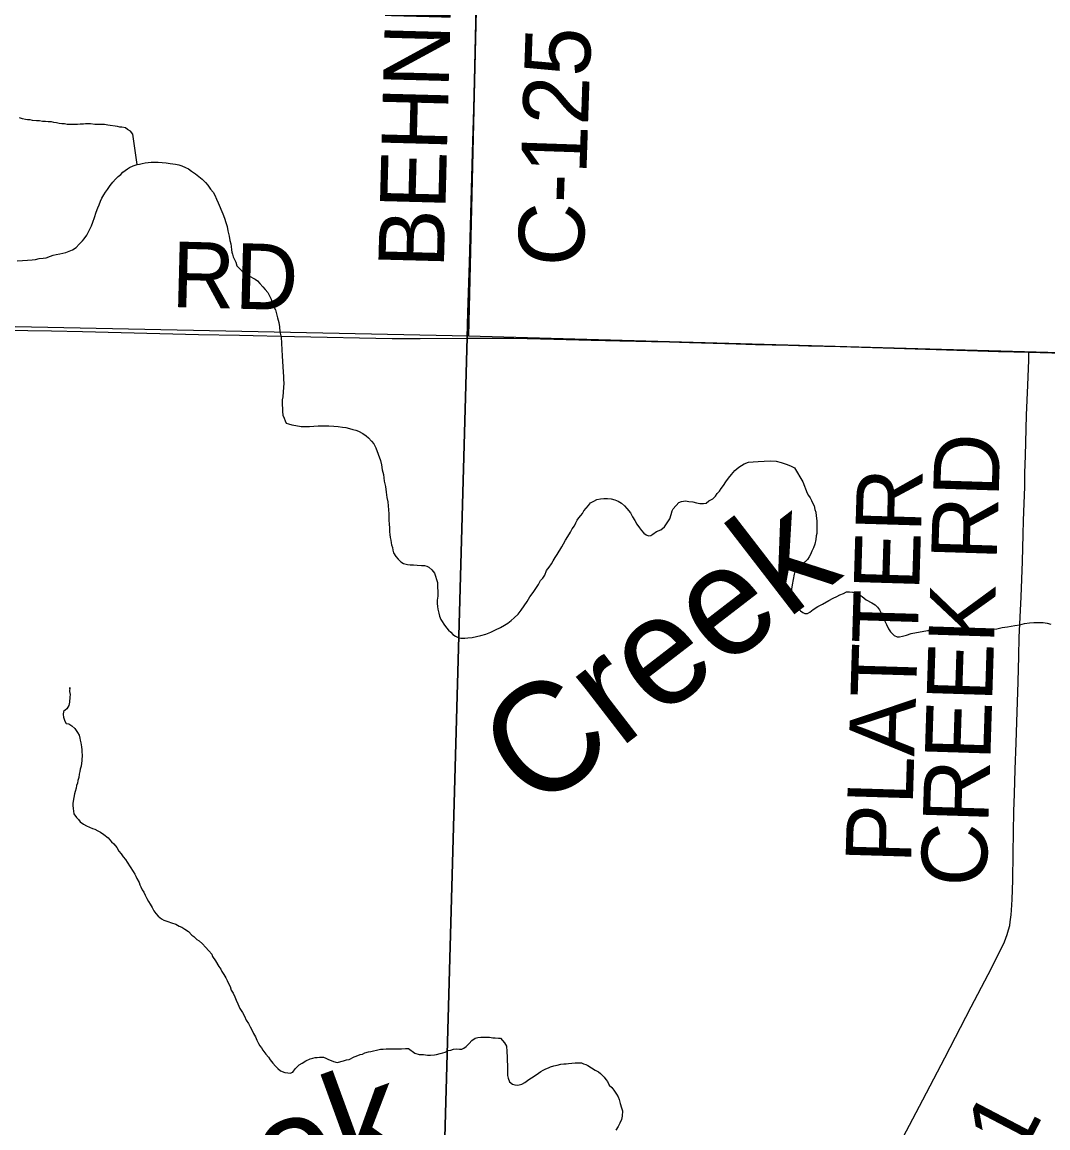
# Model space of a CAD drawing. Extents: x 2.4 to 73.1, y 4.5 to 25.6.
# Drawn here: x 30.3384 to 30.7828, y 21.8149 to 22.2941 of the extents above; entities that cross this region are included whole.
import ezdxf

# ---------------------------------------------------------------- set-up
doc = ezdxf.new("R2010")
doc.units = 0
for name, color, linetype in [('GM_X_County_Road', 7, 'Continuous'), ('GM_X_County_Road_Text', 7, 'Continuous'), ('GM_X_Interchange_Ramps', 7, 'Continuous'), ('GM_X_Minor_River', 7, 'Continuous'), ('GM_X_Minor_River_Text', 7, 'Continuous'), ('GM_X_Section', 7, 'Continuous'), ('GM_X_Township', 7, 'Continuous'), ('GM_X_Township_Road', 7, 'Continuous'), ('GM_X_Township_Road_Text', 7, 'Continuous')]:
    doc.layers.add(name, color=color, linetype=linetype)

msp = doc.modelspace()

# ---------------------------------------------------------------- linework, layer by layer
at = {"layer": 'GM_X_County_Road'}
for points in [[(30.53135, 22.15713), (30.53168, 22.16802), (30.53233, 22.18946), (30.53363, 22.23731), (30.53416, 22.25626), (30.53467, 22.2746), (30.53494, 22.28734), (30.53559, 22.31904), (30.53645, 22.3498), (30.53724, 22.38306), (30.53771, 22.40201), (30.53826, 22.42594), (30.53893, 22.45515), (30.53952, 22.48281), (30.54007, 22.5027), (30.54091, 22.54341), (30.5412, 22.55491), (30.54272, 22.61986), (30.54351, 22.65), (30.54377, 22.65984)], [(30.02726, 22.16709), (30.03446, 22.16694), (30.06678, 22.16622), (30.08667, 22.16574), (30.11464, 22.16515), (30.16499, 22.164), (30.19824, 22.16321), (30.21658, 22.16286), (30.25946, 22.16202), (30.27935, 22.16155), (30.29458, 22.16116), (30.32007, 22.16074), (30.35114, 22.16022), (30.36451, 22.15997), (30.41485, 22.15876), (30.43256, 22.15839), (30.45648, 22.15783), (30.49875, 22.15699), (30.51088, 22.1569), (30.53135, 22.15713)], [(30.53135, 22.15713), (30.54112, 22.15717), (30.55139, 22.15708), (30.56879, 22.15669), (30.58495, 22.15624), (30.59738, 22.15594), (30.61105, 22.15566), (30.61882, 22.15548), (30.62752, 22.15528), (30.63777, 22.15501), (30.64771, 22.15471), (30.6561, 22.15443), (30.67037, 22.15401), (30.67907, 22.15382), (30.69274, 22.15347), (30.7207, 22.15258), (30.73438, 22.15219), (30.7614, 22.15137), (30.77457, 22.15103)], [(30.77457, 22.15103), (30.78937, 22.15064), (30.81392, 22.14998), (30.8307, 22.14948), (30.84965, 22.14881), (30.85741, 22.14855), (30.86829, 22.14817), (30.88785, 22.14753), (30.8981, 22.14719), (30.90928, 22.14687), (30.92668, 22.14638), (30.94345, 22.14576), (30.96501, 22.14514), (30.986, 22.14442), (31.00185, 22.14396), (31.02143, 22.14323), (31.02525, 22.14309)]]:
    msp.add_lwpolyline(points, dxfattribs=at)
at = {"layer": 'GM_X_Interchange_Ramps'}
msp.add_lwpolyline([(30.32928, 21.66006), (30.35104, 21.65971), (30.3697, 21.65926), (30.4615, 21.65688), (30.51723, 21.65555), (30.53123, 22.15741), (30.53156, 22.1683), (30.53221, 22.18973), (30.53352, 22.23759), (30.53404, 22.25654), (30.53455, 22.27487), (30.53482, 22.28762), (30.53547, 22.31932)], dxfattribs=at)
at = {"layer": 'GM_X_Minor_River'}
for points in [[(30.38825, 22.23232), (30.38636, 22.24547), (30.38543, 22.24681), (30.38411, 22.24759), (30.38317, 22.24818), (30.38166, 22.24858), (30.3807, 22.24859), (30.37976, 22.2488), (30.37558, 22.24944), (30.37406, 22.24965), (30.37216, 22.24968), (30.37083, 22.2497), (30.36988, 22.24972), (30.36798, 22.24994), (30.36703, 22.24995), (30.36589, 22.24997), (30.36494, 22.2498), (30.36361, 22.24982), (30.36246, 22.24965), (30.36113, 22.24967), (30.35942, 22.2497), (30.3579, 22.24972), (30.35676, 22.24993), (30.35562, 22.24995), (30.35448, 22.25016), (30.35335, 22.25036), (30.35221, 22.25057), (30.35107, 22.25078), (30.34974, 22.2508), (30.3486, 22.25101), (30.34727, 22.25103), (30.34594, 22.25124), (30.34461, 22.25126), (30.3429, 22.25148), (30.34196, 22.25169), (30.34081, 22.2517), (30.33987, 22.25191), (30.33854, 22.25212), (30.33721, 22.25252)], [(30.33624, 22.1906), (30.33853, 22.19075), (30.34081, 22.1909), (30.34272, 22.19106), (30.34424, 22.19123), (30.34577, 22.19158), (30.34748, 22.19175), (30.34882, 22.19192), (30.35073, 22.19265), (30.35187, 22.19301), (30.35321, 22.19337), (30.35474, 22.19372), (30.35607, 22.19389), (30.35741, 22.19425), (30.35875, 22.1948), (30.36028, 22.19534), (30.36182, 22.19646), (30.36317, 22.19777), (30.36453, 22.19926), (30.3653, 22.2002), (30.36647, 22.2017), (30.36843, 22.20585), (30.36903, 22.20736), (30.36982, 22.20944), (30.37043, 22.21171), (30.37122, 22.2136), (30.37181, 22.21492), (30.3724, 22.21643), (30.37299, 22.21775), (30.37378, 22.21926), (30.37456, 22.22038), (30.37533, 22.22151), (30.3765, 22.2232), (30.37767, 22.2247), (30.37883, 22.22602), (30.37999, 22.22714), (30.38114, 22.22807), (30.38211, 22.229), (30.38403, 22.23049), (30.38499, 22.23105), (30.38653, 22.23178), (30.38825, 22.23232), (30.3892, 22.2325), (30.39035, 22.23286), (30.39168, 22.23303), (30.39301, 22.2332), (30.39435, 22.23337), (30.39587, 22.23334), (30.39739, 22.23332), (30.3991, 22.23329)], [(30.3991, 22.23329), (30.40081, 22.23307), (30.40252, 22.23286), (30.40479, 22.23244), (30.40631, 22.23222), (30.40764, 22.23182), (30.40915, 22.23104), (30.41047, 22.23045), (30.41179, 22.22948), (30.41348, 22.22831), (30.41498, 22.22715), (30.41648, 22.22598), (30.41779, 22.22463), (30.41892, 22.22347), (30.42003, 22.22174), (30.42115, 22.2204), (30.42189, 22.21906), (30.42263, 22.21733), (30.42336, 22.2158), (30.42538, 22.21102), (30.42611, 22.20911), (30.42665, 22.2072), (30.42719, 22.20548), (30.42755, 22.20357), (30.42808, 22.20129), (30.42843, 22.19938), (30.42879, 22.19804), (30.42896, 22.1969), (30.42913, 22.19538), (30.4293, 22.19443), (30.42948, 22.19347), (30.42984, 22.19233), (30.43039, 22.19118), (30.43094, 22.19003), (30.43149, 22.1885), (30.43262, 22.18734), (30.43374, 22.18618), (30.43486, 22.18522), (30.43618, 22.18444), (30.4375, 22.18365), (30.43844, 22.18307), (30.43939, 22.18267), (30.44033, 22.1819), (30.44145, 22.18074), (30.44276, 22.17939), (30.44369, 22.17823), (30.44481, 22.17689), (30.44574, 22.17516), (30.44629, 22.17401), (30.44665, 22.17268), (30.44738, 22.17095), (30.44812, 22.16942), (30.44866, 22.1677), (30.44902, 22.16599), (30.44955, 22.16389), (30.4499, 22.16198), (30.45006, 22.15989), (30.4506, 22.1576), (30.45075, 22.15494), (30.45089, 22.15209), (30.45104, 22.14943), (30.4515, 22.14239), (30.45166, 22.14049), (30.45164, 22.13916), (30.4518, 22.13763), (30.45158, 22.13574), (30.45155, 22.13384), (30.45133, 22.13175), (30.45112, 22.13042), (30.4511, 22.12909), (30.45108, 22.12815), (30.45125, 22.12681), (30.45123, 22.12529), (30.4514, 22.12377), (30.45195, 22.12243), (30.45231, 22.12129), (30.45287, 22.12033), (30.45381, 22.11993), (30.45532, 22.11953), (30.45703, 22.11931), (30.45931, 22.11889), (30.46121, 22.11886), (30.46292, 22.11883), (30.46483, 22.11899), (30.46673, 22.11915), (30.46882, 22.11912), (30.47129, 22.11908), (30.47339, 22.11905), (30.47528, 22.11883), (30.47718, 22.11861), (30.4787, 22.11839), (30.48021, 22.11799), (30.48173, 22.11758), (30.48305, 22.11718), (30.48419, 22.11678), (30.48608, 22.1158), (30.48739, 22.11483), (30.48852, 22.11386), (30.48983, 22.11251), (30.49076, 22.11136), (30.49168, 22.10963)], [(30.49168, 22.10963), (30.49369, 22.10409), (30.49404, 22.10218), (30.49439, 22.10009), (30.49492, 22.09799), (30.49526, 22.09513), (30.4958, 22.09285), (30.49614, 22.09037), (30.49648, 22.08809), (30.49683, 22.08618), (30.497, 22.08447), (30.49716, 22.08275), (30.49732, 22.08104), (30.4973, 22.07971), (30.49728, 22.07819), (30.49744, 22.07648), (30.49761, 22.07496), (30.49758, 22.07325), (30.49775, 22.0721), (30.49792, 22.07077), (30.49809, 22.06963), (30.49827, 22.06849), (30.49844, 22.06753), (30.4988, 22.06639), (30.49898, 22.06524), (30.49934, 22.0641), (30.50027, 22.06256), (30.50139, 22.06141), (30.50251, 22.06025), (30.50364, 22.05947), (30.50535, 22.05906), (30.50648, 22.05885), (30.508, 22.05883), (30.50953, 22.0588), (30.51142, 22.05858), (30.51275, 22.05856), (30.5137, 22.05836), (30.51465, 22.05796), (30.51596, 22.0568), (30.51708, 22.05526), (30.51744, 22.05393), (30.51799, 22.05259), (30.51835, 22.05125), (30.51844, 22.04536), (30.51823, 22.04365), (30.5182, 22.04213), (30.51837, 22.0408), (30.51854, 22.03966), (30.5189, 22.03794), (30.51926, 22.03661), (30.51981, 22.03527), (30.52036, 22.03431), (30.5211, 22.03316), (30.52222, 22.03162), (30.52316, 22.03065), (30.52409, 22.02969), (30.52503, 22.02872), (30.52616, 22.02795), (30.52729, 22.02736), (30.52843, 22.02715), (30.53014, 22.02712), (30.53147, 22.02729), (30.53338, 22.02745), (30.53528, 22.0278), (30.53719, 22.02834), (30.5393, 22.02887), (30.5414, 22.02979), (30.54351, 22.03071), (30.54562, 22.03181), (30.54734, 22.03273), (30.54888, 22.03366), (30.55023, 22.03478), (30.55158, 22.0359), (30.55332, 22.03758), (30.55467, 22.03927), (30.55584, 22.04115), (30.5572, 22.04302), (30.55838, 22.0451), (30.55974, 22.04697), (30.56091, 22.04866), (30.56207, 22.05036), (30.56305, 22.05205), (30.56402, 22.05317), (30.5648, 22.05449), (30.56559, 22.05638), (30.56676, 22.05788), (30.56773, 22.05938), (30.56851, 22.0607), (30.56929, 22.06202), (30.57027, 22.06333), (30.57222, 22.06672), (30.573, 22.06804), (30.57379, 22.06955), (30.57476, 22.07124), (30.57593, 22.07312), (30.57672, 22.07444), (30.57769, 22.07575), (30.57828, 22.07707), (30.57887, 22.0782), (30.57964, 22.07933), (30.58042, 22.08027)], [(30.58042, 22.08027), (30.5812, 22.08121), (30.58178, 22.08234), (30.58275, 22.08346), (30.58372, 22.08459), (30.58469, 22.08571), (30.58603, 22.08645), (30.58738, 22.08719), (30.5889, 22.08754), (30.59043, 22.08771), (30.59195, 22.08768), (30.59366, 22.08747), (30.59517, 22.08706), (30.59668, 22.08647), (30.598, 22.08569), (30.59932, 22.08452), (30.60044, 22.08337), (30.60193, 22.08144), (30.60285, 22.07972), (30.60378, 22.07818), (30.6047, 22.07646), (30.60582, 22.07492), (30.60675, 22.07376), (30.60769, 22.07261), (30.60882, 22.07183), (30.60976, 22.07143), (30.61071, 22.07161), (30.61167, 22.07216), (30.61321, 22.07328), (30.61513, 22.07401), (30.61667, 22.07531), (30.61725, 22.07625), (30.61842, 22.07794), (30.61901, 22.07889), (30.61961, 22.08077), (30.62001, 22.08229), (30.62041, 22.08323), (30.62292, 22.08585), (30.62407, 22.0864), (30.62578, 22.08657), (30.6273, 22.08635), (30.62901, 22.08613), (30.63052, 22.08573), (30.63204, 22.08551), (30.63356, 22.08549), (30.63471, 22.08566), (30.63586, 22.08659), (30.63759, 22.08751), (30.63875, 22.08864), (30.63953, 22.08976), (30.64049, 22.09089), (30.64127, 22.09201), (30.64225, 22.09333), (30.64322, 22.09483), (30.64439, 22.09652), (30.64574, 22.09802), (30.6471, 22.09971), (30.64883, 22.1012), (30.65114, 22.10268), (30.65305, 22.10341), (30.65515, 22.10357), (30.65724, 22.10372), (30.65991, 22.10387), (30.66257, 22.10402), (30.66504, 22.10379), (30.66731, 22.10318), (30.6694, 22.10258), (30.67129, 22.10179), (30.67298, 22.101), (30.67669, 22.09486), (30.67852, 22.08989), (30.67907, 22.08893), (30.67982, 22.08797), (30.68037, 22.08682), (30.68092, 22.08548), (30.68148, 22.08452), (30.68183, 22.08281), (30.68219, 22.08166), (30.68236, 22.08014), (30.68253, 22.07918), (30.6827, 22.07785), (30.68268, 22.07633), (30.68266, 22.075), (30.68264, 22.07386), (30.68262, 22.07253), (30.68241, 22.0714), (30.6822, 22.06988), (30.68178, 22.0678), (30.68119, 22.06629), (30.68059, 22.06477), (30.68, 22.06345), (30.67941, 22.06232), (30.67864, 22.0612)], [(30.67864, 22.0612), (30.67748, 22.06008), (30.67632, 22.05915), (30.67516, 22.05802), (30.6742, 22.05709), (30.67323, 22.05596), (30.67283, 22.05483), (30.672, 22.05029), (30.67178, 22.04839), (30.67175, 22.04687), (30.67193, 22.04573), (30.6721, 22.04477), (30.67228, 22.04382), (30.67264, 22.04286), (30.67356, 22.04095), (30.6745, 22.04017), (30.67563, 22.03902), (30.67656, 22.03824), (30.67751, 22.03784), (30.67865, 22.03783), (30.67961, 22.03838), (30.68115, 22.0395), (30.68307, 22.04079), (30.68518, 22.0419), (30.68787, 22.04338), (30.68978, 22.04449), (30.69132, 22.04522), (30.69266, 22.04596), (30.69419, 22.0465), (30.69553, 22.04724), (30.69686, 22.04722), (30.69819, 22.04701), (30.69952, 22.04661), (30.70103, 22.04601), (30.70235, 22.04523), (30.70404, 22.04368), (30.70649, 22.0425), (30.708, 22.04153), (30.70893, 22.04056), (30.70986, 22.03941), (30.71042, 22.03826), (30.71115, 22.03654), (30.71189, 22.03501), (30.71281, 22.03309), (30.71373, 22.03118), (30.71466, 22.02983), (30.71616, 22.02829), (30.71748, 22.0277), (30.71843, 22.02768), (30.71977, 22.02804), (30.72148, 22.02839), (30.72359, 22.02912), (30.73064, 22.03052), (30.73312, 22.03048), (30.7354, 22.03025), (30.73825, 22.03002), (30.74071, 22.02979), (30.74356, 22.02955), (30.74641, 22.0295), (30.74946, 22.02983), (30.75251, 22.03016), (30.75537, 22.0305), (30.75804, 22.03084), (30.7607, 22.03117), (30.763, 22.0317), (30.76528, 22.03205), (30.76852, 22.03256), (30.77062, 22.03291), (30.77272, 22.03345), (30.77482, 22.03379), (30.77672, 22.03395), (30.77882, 22.03392), (30.78072, 22.03389), (30.78242, 22.03367), (30.78413, 22.03326)], [(30.35902, 22.00574), (30.35901, 22.00517), (30.35902, 22.00574), (30.35899, 22.00403), (30.35916, 22.0027), (30.35914, 22.00156), (30.35892, 21.99947), (30.35871, 21.99796), (30.35773, 21.99645), (30.35638, 21.99533), (30.35617, 21.99401), (30.35634, 21.99286), (30.35689, 21.99114), (30.35744, 21.99018), (30.35858, 21.98998), (30.3599, 21.9892), (30.36121, 21.98803), (30.36233, 21.98631), (30.36307, 21.98516), (30.36343, 21.98382), (30.3636, 21.98287), (30.36378, 21.98172), (30.36413, 21.98001), (30.3643, 21.97868), (30.36428, 21.97773), (30.36446, 21.97658), (30.36423, 21.97412), (30.364, 21.97165), (30.3636, 21.97033), (30.36339, 21.96938), (30.36319, 21.96824), (30.36297, 21.96673), (30.36257, 21.9654), (30.36236, 21.96427), (30.36197, 21.96332), (30.36176, 21.96219), (30.36135, 21.96067), (30.36115, 21.95973), (30.36053, 21.95651), (30.36032, 21.95556), (30.36031, 21.95461), (30.36048, 21.95328), (30.36082, 21.95099), (30.36194, 21.94945), (30.36288, 21.94849), (30.36362, 21.94753), (30.36494, 21.94655), (30.36626, 21.94577), (30.36758, 21.94518), (30.3689, 21.94459), (30.36985, 21.94439), (30.37117, 21.9436), (30.3723, 21.94302), (30.3738, 21.94204), (30.37569, 21.94068), (30.37718, 21.93895), (30.37812, 21.93798), (30.37942, 21.93644), (30.38035, 21.93491), (30.38128, 21.93375), (30.38221, 21.93241), (30.38315, 21.93125), (30.38389, 21.9301), (30.38649, 21.92607), (30.38723, 21.92492), (30.3876, 21.92396), (30.38815, 21.923), (30.38907, 21.92128), (30.38944, 21.92032), (30.38981, 21.91937), (30.39035, 21.91803), (30.3911, 21.91706), (30.39165, 21.91573), (30.39239, 21.91438), (30.39313, 21.91304), (30.39387, 21.91189), (30.3948, 21.91036), (30.39554, 21.90901), (30.39628, 21.90786), (30.39741, 21.9067), (30.39872, 21.90554), (30.39985, 21.90495), (30.40155, 21.90436), (30.40306, 21.90376), (30.40496, 21.90316), (30.40647, 21.90238), (30.4076, 21.90198), (30.40892, 21.90101), (30.41042, 21.90004), (30.41192, 21.89849), (30.41286, 21.89791), (30.41417, 21.89656), (30.41511, 21.89597), (30.41661, 21.89462), (30.41792, 21.89326), (30.41923, 21.89172), (30.42054, 21.89018), (30.4209, 21.88923), (30.4222, 21.88731), (30.42369, 21.88481), (30.42443, 21.88366)], [(30.42443, 21.88366), (30.42498, 21.8827), (30.42573, 21.88136), (30.42666, 21.88001), (30.42721, 21.87887), (30.42776, 21.87753), (30.4285, 21.87618), (30.42904, 21.87466), (30.42978, 21.87331), (30.43052, 21.87178), (30.43107, 21.87025), (30.4318, 21.86872), (30.43272, 21.86662), (30.43383, 21.86489), (30.43476, 21.86335), (30.4355, 21.86163), (30.43642, 21.8601), (30.43716, 21.85876), (30.4379, 21.85741), (30.43864, 21.85588), (30.43957, 21.85435), (30.44012, 21.85301), (30.44085, 21.85148), (30.44141, 21.85052), (30.44215, 21.84956), (30.44271, 21.8486), (30.44401, 21.84687), (30.44513, 21.84552), (30.44587, 21.84437), (30.447, 21.84302), (30.44812, 21.84167), (30.44924, 21.8407), (30.45037, 21.83973), (30.45226, 21.83894), (30.45358, 21.83873), (30.45453, 21.83872), (30.45568, 21.83908), (30.45666, 21.84058), (30.45839, 21.84226), (30.45974, 21.843), (30.46127, 21.84393), (30.46319, 21.84485), (30.46434, 21.84521), (30.46529, 21.84538), (30.46624, 21.84537), (30.46719, 21.84554), (30.46891, 21.84552), (30.47004, 21.84512), (30.47117, 21.84453), (30.47231, 21.84413), (30.47325, 21.84374), (30.47496, 21.84333), (30.47763, 21.84404), (30.47897, 21.8444), (30.48011, 21.84457), (30.48222, 21.84568), (30.48318, 21.84605), (30.4849, 21.84678), (30.48585, 21.84695), (30.48681, 21.84751), (30.48853, 21.84786), (30.48948, 21.84803), (30.49063, 21.8484), (30.49196, 21.84856), (30.49368, 21.84911), (30.49483, 21.84909), (30.49616, 21.84926), (30.4973, 21.84924), (30.49825, 21.84922), (30.49996, 21.8492), (30.50091, 21.84918), (30.50186, 21.84916), (30.50281, 21.84915), (30.50453, 21.84931), (30.50586, 21.84929), (30.50849, 21.84735), (30.51038, 21.84675), (30.51228, 21.84672), (30.51399, 21.8465), (30.51532, 21.84648), (30.51704, 21.84664), (30.51799, 21.84681), (30.51952, 21.84717), (30.52067, 21.84753), (30.52162, 21.84771), (30.52296, 21.84845), (30.52411, 21.84862), (30.52525, 21.84898), (30.52659, 21.84915), (30.52792, 21.84912), (30.52887, 21.84911), (30.52983, 21.84947), (30.53079, 21.85022), (30.53214, 21.85153), (30.5333, 21.85284), (30.53465, 21.85377), (30.53579, 21.85413), (30.53713, 21.8543), (30.53865, 21.85427), (30.54093, 21.85423), (30.54226, 21.85402)], [(30.54226, 21.85402), (30.5434, 21.854), (30.54473, 21.85379), (30.54568, 21.85378), (30.54736, 21.85185), (30.54829, 21.85032), (30.54844, 21.84803), (30.54859, 21.84556), (30.54857, 21.84385), (30.54873, 21.84233), (30.54871, 21.841), (30.5487, 21.84005), (30.54867, 21.83872), (30.54866, 21.83758), (30.54902, 21.83643), (30.54957, 21.83491), (30.55088, 21.83393), (30.55183, 21.83354), (30.55316, 21.83352), (30.55488, 21.83387), (30.55622, 21.83461), (30.55795, 21.83591), (30.5591, 21.83665), (30.56103, 21.83795), (30.56218, 21.83869), (30.56314, 21.83943), (30.5641, 21.83999), (30.56525, 21.84054), (30.5664, 21.8409), (30.56736, 21.84146), (30.56869, 21.84182), (30.57022, 21.84217), (30.57175, 21.84253), (30.57308, 21.8427), (30.57403, 21.84268), (30.57517, 21.84285), (30.57803, 21.84318), (30.57936, 21.84316), (30.58069, 21.84314), (30.58164, 21.84275), (30.58258, 21.84235), (30.58353, 21.84195), (30.58503, 21.84098), (30.58673, 21.84), (30.58805, 21.83922), (30.58899, 21.83845), (30.59049, 21.8369), (30.59123, 21.83594), (30.59198, 21.83498), (30.59271, 21.83345), (30.59384, 21.83248), (30.59477, 21.83132), (30.59589, 21.8296), (30.59663, 21.82844), (30.59699, 21.8273), (30.59754, 21.82558), (30.59808, 21.82367), (30.59844, 21.82233), (30.5984, 21.82005), (30.598, 21.81854), (30.5974, 21.81703), (30.59662, 21.81552), (30.59564, 21.81402)]]:
    msp.add_lwpolyline(points, dxfattribs=at)
at = {"layer": 'GM_X_Section'}
for points in [[(30.03874, 22.66769), (30.54366, 22.66127), (30.53178, 22.158), (30.02677, 22.1684)], [(30.54366, 22.66127), (30.5437, 22.66298), (31.04027, 22.64802), (31.02363, 22.1441), (30.53178, 22.158)]]:
    msp.add_lwpolyline(points, close=True, dxfattribs=at)
at = {"layer": 'GM_X_Township'}
msp.add_lwpolyline([(30.53547, 22.31932), (30.53482, 22.28762), (30.53455, 22.27487), (30.53404, 22.25654), (30.53352, 22.23759), (30.53221, 22.18973), (30.53156, 22.1683), (30.53123, 22.15741), (30.51723, 21.65555), (30.52062, 21.65547), (30.52864, 21.65537), (30.53536, 21.65517), (30.54266, 21.65493), (30.87898, 21.6465), (31.00992, 21.6427), (31.01567, 21.64273), (31.03229, 21.64244), (31.0882, 21.64098), (31.12703, 21.64008), (31.18339, 21.63943)], dxfattribs=at)
at = {"layer": 'GM_X_Township_Road'}
for points in [[(30.76688, 21.90725), (30.76707, 21.90928), (30.76731, 21.9139), (30.76761, 21.92228), (30.7677, 21.93385), (30.76787, 21.943), (30.76802, 21.95196), (30.76825, 21.95972), (30.7686, 21.97027), (30.76898, 21.98176), (30.76929, 21.99076), (30.76994, 22.00815), (30.77021, 22.01934), (30.77032, 22.02741), (30.77115, 22.0451), (30.77174, 22.06032), (30.77207, 22.07209), (30.77229, 22.07816), (30.77254, 22.08553), (30.77273, 22.09266), (30.77286, 22.09856), (30.77307, 22.10633), (30.77323, 22.11192), (30.77359, 22.12372), (30.77412, 22.13676), (30.77446, 22.14763), (30.77457, 22.15103)], [(30.71574, 21.80262), (30.72858, 21.82712), (30.73811, 21.84529), (30.74951, 21.8674), (30.75692, 21.88141), (30.76171, 21.89083), (30.76393, 21.89558), (30.76521, 21.89872), (30.76577, 21.90073), (30.76626, 21.90262), (30.76651, 21.90426), (30.76688, 21.90725)]]:
    msp.add_lwpolyline(points, dxfattribs=at)

# ---------------------------------------------------------------- texts
at = {"layer": 'GM_X_County_Road_Text'}
for s, rotation, p in [('BEHNFELDT', 88.4739, (30.52109, 22.18732)), ('C-125', 88.0734, (30.58149, 22.1879)), ('RD', 358.5175, (30.40286, 22.17063))]:
    msp.add_text(s, height=0.028409, rotation=rotation, dxfattribs=at).set_placement(p)
at = {"layer": 'GM_X_Minor_River_Text'}
for height, rotation, p in [(0.047366, 37.6433, (30.56089, 21.95103)), (0.04737, 20.0457, (30.35181, 21.74263))]:
    msp.add_text('Creek', height=height, rotation=rotation, dxfattribs=at).set_placement(p)
at = {"layer": 'GM_X_Township_Road_Text'}
for s, height, rotation, p in [('CREEK RD', 0.028409, 88.185, (30.75608, 21.91919)), ('PLATTER', 0.028409, 88.2787, (30.72348, 21.92933)), ('1', 0.02841, 62.3946, (30.7709, 21.80128))]:
    msp.add_text(s, height=height, rotation=rotation, dxfattribs=at).set_placement(p)

doc.saveas('drawing.dxf')
